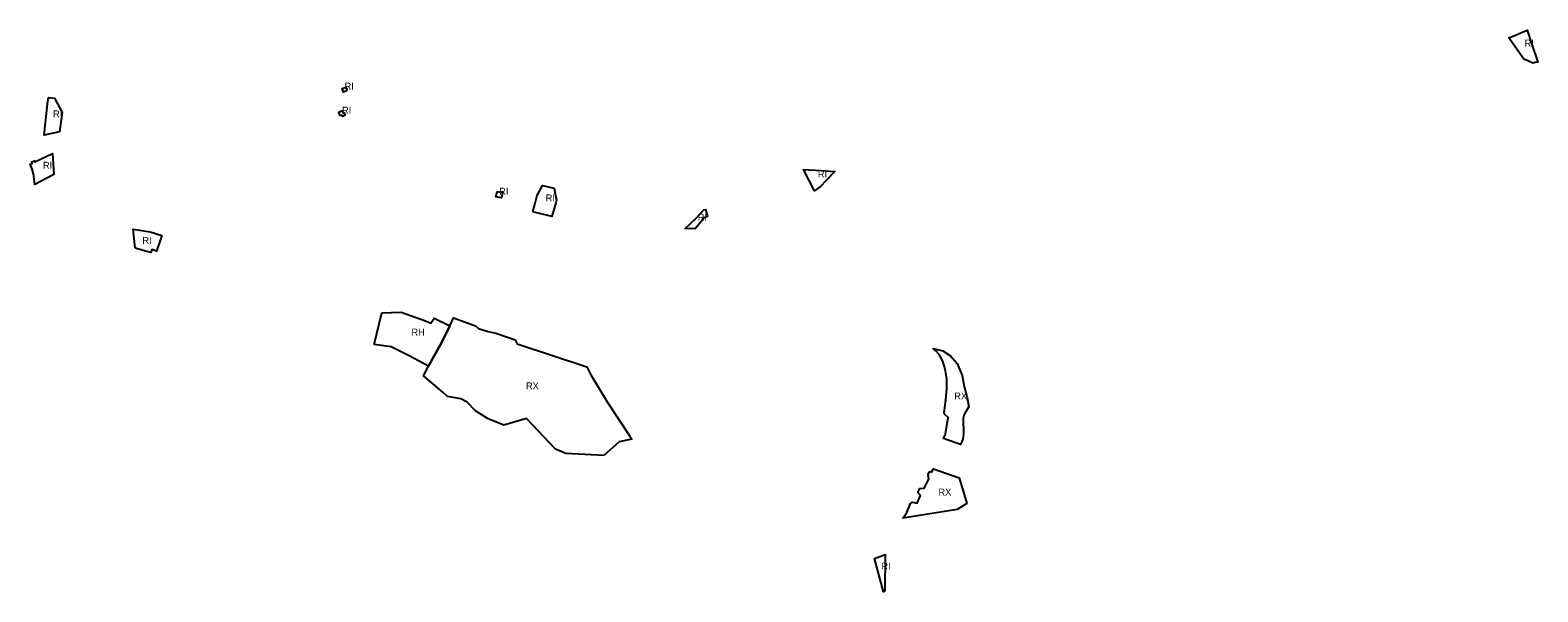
# Model space of a CAD drawing. Extents: x -477010 to -466219, y -1158799 to -1150161.
# Drawn here: x -468188 to -466219, y -1153348 to -1152614 of the extents above; entities that cross this region are included whole.
import ezdxf

# ---------------------------------------------------------------- set-up
doc = ezdxf.new("R2010")
doc.units = 0
for name, color, linetype in [('16', 7, 'Continuous'), ('19', 7, 'Continuous'), ('25', 7, 'Continuous')]:
    doc.layers.add(name, color=color, linetype=linetype)

msp = doc.modelspace()

# ---------------------------------------------------------------- linework, layer by layer
at = {"layer": '16'}
msp.add_lwpolyline([(-467738.37, -1153024.83), (-467728.25, -1152983.43), (-467703.29, -1152982.38), (-467677.4, -1152991.52), (-467670.25, -1152994.04), (-467664.17, -1152996.89), (-467659.93, -1152990.04), (-467639.75, -1153000.27), (-467649.88, -1153021.59), (-467662.04, -1153043.52), (-467667.44, -1153052.83), (-467692.84, -1153039.64), (-467713.75, -1153028.79), (-467716.2, -1153027.52)], close=True, dxfattribs=at)
at = {"layer": '19'}
for points in [[(-466254.6, -1152627.22), (-466256.7, -1152624.18), (-466247.52, -1152620.26), (-466232.97, -1152614.05), (-466227.2, -1152631.34), (-466219.03, -1152655.82), (-466222.39, -1152656.43), (-466225.59, -1152657.01), (-466232.18, -1152654.27), (-466237.37, -1152652.11)], [(-467773.78, -1152693.05), (-467778.44, -1152694.89), (-467780.21, -1152690.42), (-467775.55, -1152688.58)], [(-468164.24, -1152706.74), (-468163.63, -1152702.13), (-468155.57, -1152702.84), (-468145.81, -1152721.73), (-468149.09, -1152746.69), (-468169, -1152751.09)], [(-467779.98, -1152719.22), (-467778.69, -1152722.44), (-467777.36, -1152721.91), (-467776.04, -1152725.22), (-467779.73, -1152726.85), (-467780.49, -1152724.93), (-467782.54, -1152725.75), (-467784.43, -1152721)], [(-468185, -1152795.56), (-468187.5, -1152789.03), (-468184.72, -1152788.04), (-468185.38, -1152786.16), (-468181.7, -1152784.85), (-468181.31, -1152785.94), (-468158.43, -1152775.21), (-468156.51, -1152802.49), (-468181.35, -1152815.48), (-468183.08, -1152801.89)], [(-467170.41, -1152796.58), (-467162.14, -1152797.08), (-467154.69, -1152797.52), (-467136.77, -1152798.59), (-467148.18, -1152810.3), (-467155.76, -1152818.07), (-467163.3, -1152823.87), (-467177.97, -1152796.13)], [(-467570.83, -1152826.12), (-467572.27, -1152833.15), (-467579.43, -1152831.7), (-467577.95, -1152824.66)], [(-467531.12, -1152851.24), (-467528.5, -1152841.63), (-467525.34, -1152829.71), (-467522.9, -1152825.1), (-467518.51, -1152816.93), (-467507.46, -1152819.52), (-467503.31, -1152820.49), (-467501.97, -1152827.9), (-467500.46, -1152836.09), (-467501.35, -1152839.44), (-467506.32, -1152857.38)], [(-467307.59, -1152859.03), (-467319.03, -1152873.65), (-467332.15, -1152873.17), (-467317.82, -1152859.5), (-467307.79, -1152848.88), (-467305.9, -1152848.45), (-467302.99, -1152857.39)], [(-468030.97, -1152877.66), (-468015.76, -1152882.35), (-468017.06, -1152886.15), (-468022.69, -1152902.62), (-468028.74, -1152900.55), (-468030.14, -1152904.65), (-468033.89, -1152903.52), (-468048.72, -1152899.07), (-468050.41, -1152898.2), (-468053.19, -1152873.94)], [(-467071.53, -1153346.2), (-467073.35, -1153347.71), (-467085.252, -1153304.034), (-467071.22, -1153298.94)]]:
    msp.add_lwpolyline(points, close=True, dxfattribs=at)
at = {"layer": '25'}
for points in [[(-467438.71, -1153169.54), (-467487.96, -1153167.06), (-467501.78, -1153161.2), (-467539.42, -1153121.13), (-467569.06, -1153129.88), (-467589.55, -1153121.58), (-467606.21, -1153111.18), (-467617, -1153099.95), (-467625.4, -1153095.39), (-467642.58, -1153092.37), (-467648.12, -1153087.5), (-467673.74, -1153065.57), (-467667.44, -1153052.83), (-467662.04, -1153043.52), (-467649.88, -1153021.59), (-467639.75, -1153000.27), (-467634.68, -1152989.8), (-467606.16, -1153000.44), (-467602.08, -1153003.9), (-467589.34, -1153007.47), (-467579.61, -1153009.64), (-467561.67, -1153015.94), (-467554.16, -1153018.58), (-467551.77, -1153023.64), (-467460.54, -1153054.02), (-467455.39, -1153064.24), (-467434.07, -1153099.35), (-467404.75, -1153144.44), (-467402.14, -1153148.48), (-467414.52, -1153150.85), (-467418.48, -1153151.89)], [(-466995.82, -1153032.74), (-466985.86, -1153039.58), (-466977.11, -1153049.5), (-466970.47, -1153065), (-466968.18, -1153079.51), (-466964.17, -1153094.23), (-466962.11, -1153106.03), (-466967.38, -1153114.53), (-466968.52, -1153117.18), (-466969.2, -1153120.71), (-466968.92, -1153141.15), (-466969.95, -1153148.19), (-466972.79, -1153155.34), (-466995.23, -1153147.52), (-466992.46, -1153141.56), (-466988.98, -1153119.77), (-466993.64, -1153115.51), (-466994.04, -1153113.99), (-466992.19, -1153096.96), (-466990.68, -1153082.47), (-466990.45, -1153077.55), (-466990.51, -1153073.3), (-466990.83, -1153069.34), (-466992.45, -1153058.87), (-466993.58, -1153053.98), (-466995.24, -1153048.09), (-466997.16, -1153043.89), (-467000.82, -1153037.73), (-467005.2, -1153032.95), (-467008.61, -1153029.85)], [(-467010.51, -1153191.45), (-467008.01, -1153187.11), (-466974.61, -1153198.72), (-466964.62, -1153232.32), (-466977.37, -1153240.1), (-467048.29, -1153251.57), (-467046.62, -1153249.89), (-467044.47, -1153246.89), (-467043, -1153244.06), (-467038.12, -1153232.35), (-467035.68, -1153230.41), (-467029.54, -1153231.71), (-467025.24, -1153221.97), (-467028.64, -1153217.81), (-467026.11, -1153212.86), (-467020.15, -1153212.39), (-467014.25, -1153200.65), (-467015.15, -1153194.49), (-467013.91, -1153191.38), (-467012.62, -1153190.72)]]:
    msp.add_lwpolyline(points, close=True, dxfattribs=at)

# ---------------------------------------------------------------- texts
at = {"layer": '16'}
msp.add_text('RH', height=9, dxfattribs=at).set_placement((-467689.6985, -1153012.89))
at = {"layer": '19'}
for p in [(-466236.314, -1152635.47), (-467776.93, -1152691.73), (-467780.268, -1152723.116), (-468157.579, -1152727.961), (-468170.774, -1152794.997), (-467159.043, -1152806.427), (-467575.057, -1152828.905), (-467514.427, -1152837.718), (-467315.867, -1152862.797), (-468040.9401, -1152893.2692), (-467076.027, -1153318.474)]:
    msp.add_text('RI', height=9, dxfattribs=at).set_placement(p)
at = {"layer": '25'}
for p in [(-467540.1435, -1153083.166), (-466980.9225, -1153096.366), (-467001.5365, -1153221.875)]:
    msp.add_text('RX', height=9, dxfattribs=at).set_placement(p)

doc.saveas('drawing.dxf')
